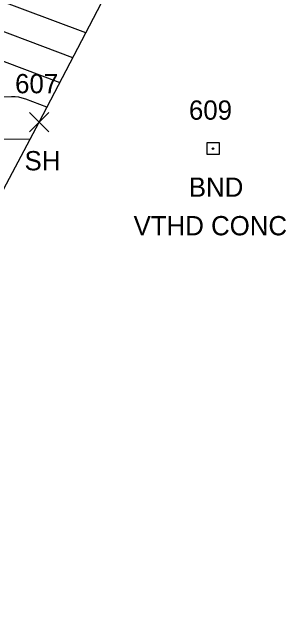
# Model space of a CAD drawing. Extents: x 1650836 to 1652450, y 332578 to 333908.
# Drawn here: x 1652421.5 to 1652449.9, y 332642.9 to 332704.6 of the extents above; entities that cross this region are included whole.
import ezdxf

# ---------------------------------------------------------------- set-up
doc = ezdxf.new("R2010")
doc.units = 0
for name, color, linetype in [('L_A', 7, 'Continuous'), ('L_I', 7, 'Continuous'), ('L_TIC', 7, 'Continuous'), ('LSOGCMI', 7, 'Continuous'), ('LSOGP', 7, 'Continuous'), ('M_A', 7, 'Continuous'), ('M_C', 7, 'Continuous'), ('M_I', 7, 'Continuous'), ('MHBP', 7, 'Continuous')]:
    doc.layers.add(name, color=color, linetype=linetype)

msp = doc.modelspace()

# ---------------------------------------------------------------- linework, layer by layer
at = {"layer": 'L_TIC'}
for points in [[(1652423.287, 332692.179), (1652425.287, 332694.179)], [(1652425.287, 332692.179), (1652423.287, 332694.179)]]:
    msp.add_lwpolyline(points, dxfattribs=at)
at = {"layer": 'LSOGCMI'}
for points in [[(1652397.718, 332710.992), (1652408.846, 332701.474), (1652409.666, 332700.886), (1652410.548, 332700.468), (1652411.493, 332700.222), (1652412.499, 332700.148), (1652416.665, 332700.194), (1652417.687, 332700.158), (1652418.692, 332700.028), (1652419.681, 332699.805), (1652420.653, 332699.488), (1652426.437, 332697.304)], [(1652425.098, 332694.736), (1652422.915, 332695.56), (1652422.548, 332695.68), (1652422.175, 332695.764), (1652421.796, 332695.813), (1652421.41, 332695.827), (1652414.043, 332695.746), (1652412.726, 332695.844), (1652411.491, 332696.165), (1652410.337, 332696.711), (1652409.265, 332697.481), (1652394.708, 332709.931)], [(1652423.359, 332691.429), (1652415.014, 332691.338), (1652413.665, 332691.438), (1652412.4, 332691.767), (1652411.217, 332692.327), (1652410.119, 332693.116), (1652391.293, 332709.217)], [(1652429.114, 332702.44), (1652412.546, 332708.696)], [(1652427.776, 332699.872), (1652416.607, 332704.09), (1652415.929, 332704.311), (1652415.24, 332704.466), (1652414.54, 332704.556), (1652413.827, 332704.581), (1652410.955, 332704.55), (1652410.259, 332704.601), (1652409.606, 332704.772)]]:
    msp.add_lwpolyline(points, dxfattribs=at)
at = {"layer": 'LSOGP'}
msp.add_lwpolyline([(1652279.734, 332615.362), (1652315.79, 332612.523), (1652339.409, 332598.399), (1652346.545, 332595.098), (1652361.354, 332588.241), (1652369.183, 332583.057), (1652370.294, 332595.861), (1652377.083, 332609.462), (1652382.141, 332616.979), (1652386.916, 332625.064), (1652388.914, 332629.021), (1652395.364, 332640.33), (1652402.111, 332652.828), (1652402.772, 332654.006), (1652404.073, 332656.539), (1652408.76, 332665.713), (1652415.318, 332676.268), (1652424.287, 332693.179), (1652433.14, 332710.163), (1652407.488, 332714.435), (1652390.75, 332724.392), (1652340.004, 332757.28), (1652322.392, 332778.396), (1652286.244, 332816.269)], dxfattribs=at)
at = {"layer": 'MHBP'}
msp.add_lwpolyline([(1652441.681, 332691.061), (1652442.931, 332691.061), (1652442.931, 332689.811), (1652441.681, 332689.811)], close=True, dxfattribs=at)
msp.add_circle((1652442.306, 332690.436), 0.0833, dxfattribs=at)

# ---------------------------------------------------------------- texts
at = {"layer": 'L_A'}
msp.add_text('SH', height=2, dxfattribs=at).set_placement((1652422.775, 332688.179))
at = {"layer": 'L_I'}
msp.add_text('607', height=2, dxfattribs=at).set_placement((1652421.799, 332696.179))
at = {"layer": 'M_A'}
msp.add_text('BND', height=2, dxfattribs=at).set_placement((1652439.794, 332685.436))
at = {"layer": 'M_C'}
msp.add_text('VTHD CONC', height=2, dxfattribs=at).set_placement((1652434.078, 332681.436))
at = {"layer": 'M_I'}
msp.add_text('609', height=2, dxfattribs=at).set_placement((1652439.81, 332693.436))

doc.saveas('drawing.dxf')
